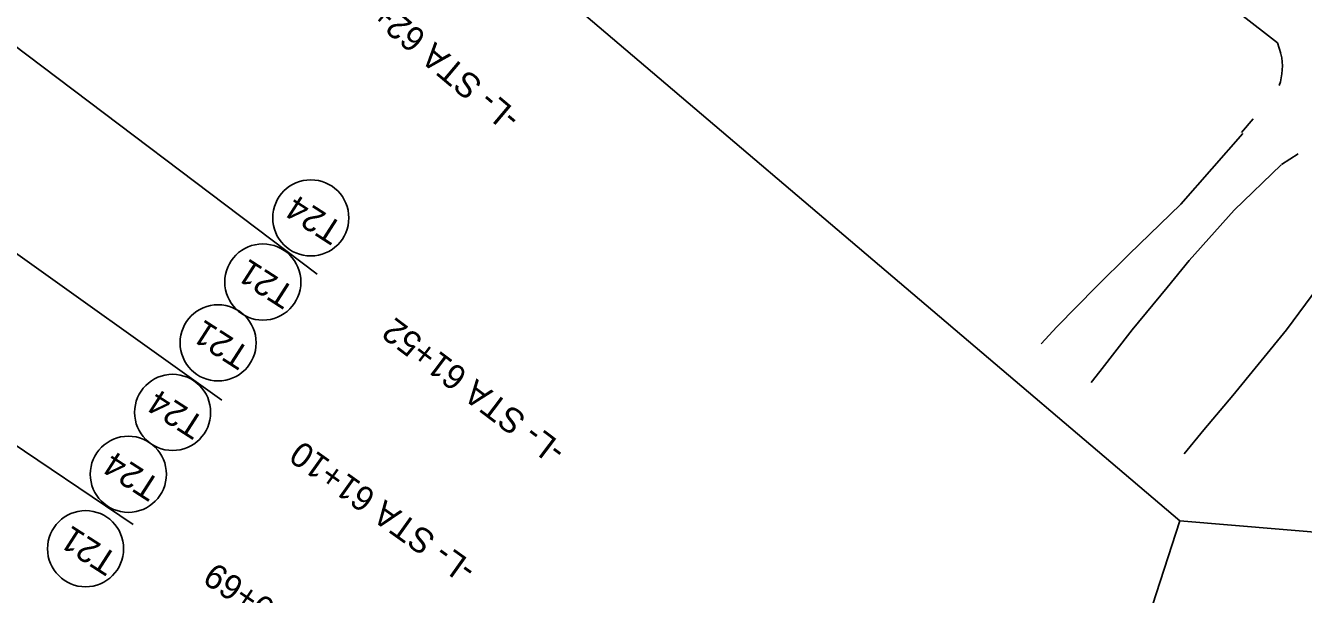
# Model space of a CAD drawing. Extents: x 553958 to 562499, y 493978 to 516388.
# Drawn here: x 557610 to 557919.7, y 506521.5 to 506659.2 of the extents above; entities that cross this region are included whole.
import ezdxf

# ---------------------------------------------------------------- set-up
doc = ezdxf.new("R2010")
doc.units = 0
for name, color, linetype in [('Default', 7, 'Continuous'), ('Prop Approach Slab', 7, 'Continuous'), ('Prop EOT', 7, 'Continuous'), ('Prop Erosion Rip Rap Class II Label', 7, 'Continuous'), ('Raster_Level_0', 7, 'Continuous'), ('Scratch_Level_0', 7, 'Continuous'), ('Scratch_Level_3', 7, 'Continuous'), ('Sheet Plan CELL', 7, 'Continuous'), ('Sheet Plot Border Inside CELL', 7, 'Continuous')]:
    doc.layers.add(name, color=color, linetype=linetype)

msp = doc.modelspace()

# ---------------------------------------------------------------- linework, layer by layer
at = {"layer": 'Default'}
msp.add_line((557904.66, 506633.35), (557907.48, 506636.65), dxfattribs=at)
at = {"layer": 'Prop Approach Slab'}
for p, q in [((557558.78, 506691.06), (557680.67, 506599.06)), ((557533.69, 506656.92), (557657.57, 506568.52)), ((557511.85, 506622.13), (557636.11, 506538.44))]:
    msp.add_line(p, q, dxfattribs=at)
at = {"layer": 'Prop Erosion Rip Rap Class II Label'}
for points in [[(557425.46, 506933.59), (557889.73, 506539.36), (558124.72, 506519.69), (558557.87, 506177.2), (558959.56, 506684.21), (558454.57, 507154), (558185.43, 507366.81), (557535.46, 507286.55), (557335.3, 506986.11)], [(557510.24, 505740.54), (557854.59, 506431.05), (557889.73, 506539.36), (557425.46, 506933.59), (557046.6, 506628.46), (556899.98, 506318.25), (557006.57, 505850.3)]]:
    msp.add_lwpolyline(points, close=True, dxfattribs=at)
at = {"layer": 'Raster_Level_0'}
msp.add_arc((558769.28, 505775.3), 1500, 139.54257, 161.63616, dxfattribs=at)
at = {"layer": 'Scratch_Level_0'}
msp.add_line((557918.4, 506628.15), (557914.4, 506625.58), dxfattribs=at)
msp.add_lwpolyline([(557914.23, 506652.41), (557913.42, 506655.03), (557884.82, 506677.31), (557858, 506698.04), (557850.33, 506704.19)], dxfattribs=at)
msp.add_ellipse((557900.84, 506649.31), major_axis=(2.73, -13.55), ratio=0.994668, start_param=1.030621, end_param=1.599093, dxfattribs=at)
at = {"layer": 'Scratch_Level_3'}
for points in [[(557905.02, 506633.08), (557889.99, 506615.95), (557877.36, 506603.78), (557869.53, 506596.09), (557859.91, 506586.3), (557856.12, 506582.2)], [(557914.29, 506625.5), (557902.93, 506614.56), (557891.96, 506602.32), (557886.69, 506595.81), (557878.19, 506585.57), (557870.32, 506575.49), (557868.29, 506572.84)], [(557890.78, 506555.54), (557895.53, 506561.33), (557902.56, 506569.71), (557915.55, 506585.6), (557926.16, 506599.82), (557929.83, 506603.29), (557931.3, 506603.42), (557932.88, 506602.84), (557940.18, 506599.09), (557942.3, 506598.31), (557945.54, 506598.1), (557946.96, 506598.09), (557948.1, 506598.27), (557949.42, 506599.61)]]:
    msp.add_lwpolyline(points, dxfattribs=at)
at = {"layer": 'Sheet Plan CELL'}
for centre in [(557679.16, 506612.66), (557667.54, 506597.14), (557656.7, 506582.42), (557645.68, 506565.58), (557634.95, 506550.61), (557624.59, 506532.59)]:
    msp.add_circle(centre, 9.22, dxfattribs=at)
at = {"layer": 'Sheet Plot Border Inside CELL'}
msp.add_arc((558771.28, 505774.06), 1491.35, 139.87766, 148.26076, dxfattribs=at)

# ---------------------------------------------------------------- texts
at = {"layer": 'Prop EOT'}
for s, rotation, p in [('-L- STA 61+52', 142.8849, (557741.3, 506557.19)), ('T24', 147.2753, (557653.89, 506563.87)), ('-L- STA 61+10', 144.4916, (557719.6, 506528.54)), ('-L- STA 60+69', 146.0414, (557699.44, 506500.26))]:
    msp.add_text(s, height=6, rotation=rotation, dxfattribs=at).set_placement(p)
at = {"layer": 'Sheet Plan CELL'}
for s, rotation, p in [('-L- STA 62+31', 139.8645, (557730.32, 506637.6)), ('T24', 147.2753, (557687.37, 506610.95)), ('T21', 147.2753, (557675.75, 506595.43)), ('T21', 147.2753, (557664.9, 506580.71)), ('T24', 147.2753, (557643.16, 506548.91)), ('T21', 147.2753, (557632.79, 506530.88))]:
    msp.add_text(s, height=6, rotation=rotation, dxfattribs=at).set_placement(p)

doc.saveas('drawing.dxf')
